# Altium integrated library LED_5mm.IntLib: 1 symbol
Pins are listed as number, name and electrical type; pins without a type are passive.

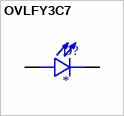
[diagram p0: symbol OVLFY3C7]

## OVLFY3C7
designator D?
LED 5mm Round Yellow 30 deg. ¦ Optek (TT Electronics) OVLFY3C7; MF: TT Electronics/Optek Technology
footprint LEDRD254W51D580H870
pins: 1 A, 2 C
